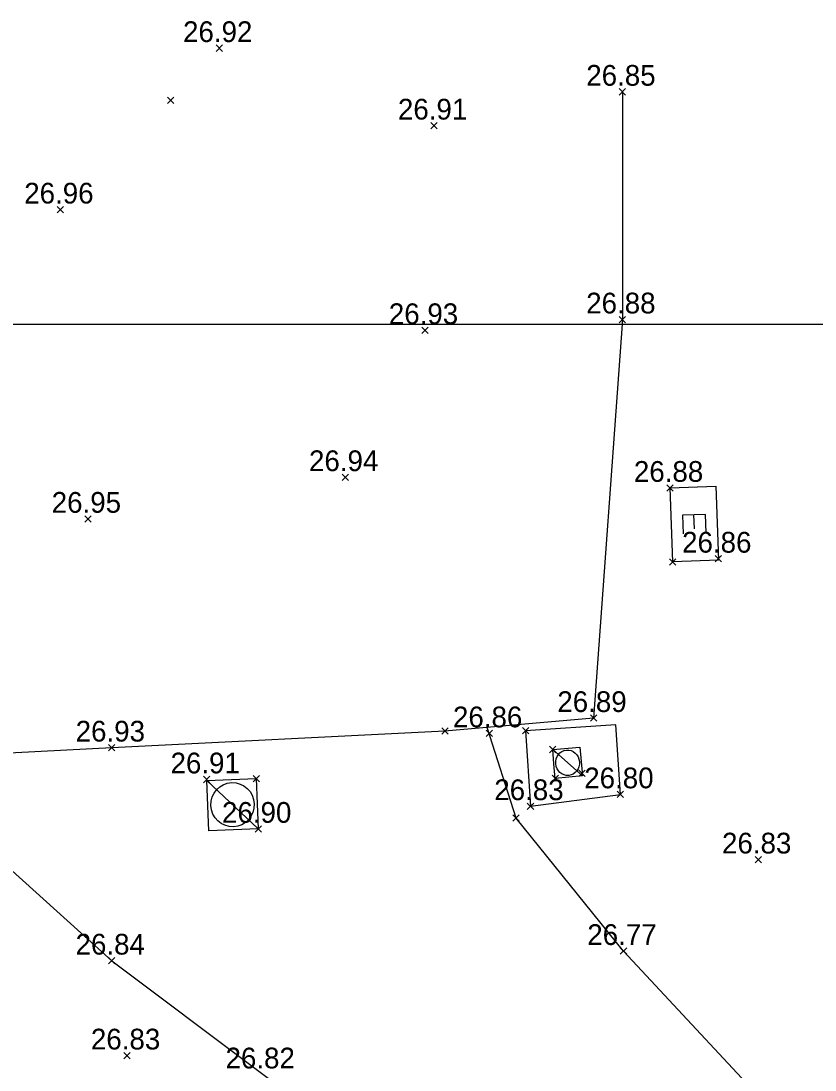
# Model space of a CAD drawing. Extents: x 37864 to 38032, y 453991 to 454052.
# Drawn here: x 37923.19 to 37934.11, y 454037.97 to 454052.39 of the extents above; entities that cross this region are included whole.
import ezdxf

# ---------------------------------------------------------------- set-up
doc = ezdxf.new("R2010")
doc.units = 0
for name, color, linetype in [('DH_CALCUL SURFACE-TEXTE', 7, 'Continuous'), ('DH_TEXTE', 7, 'Continuous'), ('GO_POTEAU', 7, 'Continuous'), ('PS_Mid', 7, 'Continuous'), ('PS_Pos', 7, 'Continuous'), ('SO_MENUISERIE EXT DOR', 7, 'Continuous'), ('SO_SANITAIRE DETAILLE', 7, 'Continuous')]:
    doc.layers.add(name, color=color, linetype=linetype)

# ---------------------------------------------------------------- blocks, each defined once
blk = doc.blocks.new('A-REGARD')
for p, q in [((0, 1), (1, 1)), ((0, 0), (1, 1)), ((0, 0), (0, 1)), ((1, 1), (1, 0)), ((0.5, 0), (0, 0)), ((1, 0), (0.5, 0))]:
    blk.add_line(p, q)
blk.add_circle((0.5, 0.5), 0.438)
blk = doc.blocks.new('V-TAMPON')
for p, q in [((0, 0), (0, 1)), ((0, 1), (1, 1)), ((1, 1), (1, 0)), ((0.375, 0.75), (0.375, 0.25)), ((0.625, 0.75), (0.375, 0.75)), ((0.562, 0.5), (0.375, 0.5)), ((0.375, 0.25), (0.625, 0.25)), ((1, 0), (0, 0))]:
    blk.add_line(p, q)
blk = doc.blocks.new('POINT_DISPLAY')
for p, q in [((-0.04375, -0.04375), (0.04375, 0.04375)), ((-0.04375, 0.04375), (0.04375, -0.04375))]:
    blk.add_line(p, q)
blk = doc.blocks.new('POINTCOT')
blk.add_blockref('POINT_DISPLAY', (0, 0))

msp = doc.modelspace()

# ---------------------------------------------------------------- linework, layer by layer
at = {"layer": 'DEFPOINTS'}
msp.add_lwpolyline([(37864.064, 453990.816), (37946.064, 453990.816), (37946.064, 454048.216), (37864.064, 454048.216)], close=True, dxfattribs=at)
at = {"layer": 'PS_Mid'}
msp.add_lwpolyline([(37930.129, 454042.632), (37930.196, 454041.595), (37931.433, 454041.758), (37931.371, 454042.712), (37930.129, 454042.632)], dxfattribs=at)
at = {"layer": 'SO_SANITAIRE DETAILLE'}
for points in [[(37931.461, 454051.412), (37931.46, 454048.283), (37931.063, 454042.806), (37929.02, 454042.628), (37924.438, 454042.4), (37918.697, 454042.102), (37913.082, 454041.936), (37907.417, 454041.715), (37901.195, 454041.497), (37895.602, 454041.336), (37888.675, 454041.141), (37884.765, 454041.024), (37878.173, 454040.907), (37873.078, 454041.057), (37866.515, 454040.532)], [(37939.024, 454033.13), (37936.384, 454034.931), (37933.79, 454037.12), (37931.475, 454039.605), (37929.998, 454041.432), (37929.601, 454042.679)], [(37921.361, 454042.24), (37924.438, 454039.473), (37928.39, 454036.508), (37931.87, 454034.006), (37934.645, 454032.123), (37937.958, 454030.315)]]:
    msp.add_lwpolyline(points, dxfattribs=at)

# ---------------------------------------------------------------- block references
at = {"layer": 'DH_CALCUL SURFACE-TEXTE', "rotation": 2.2526485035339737e-05}
for p in [(37925.916, 454052.012), (37931.461, 454051.412), (37925.247, 454051.294), (37928.871, 454050.947), (37923.732, 454049.793), (37931.46, 454048.283), (37928.746, 454048.136), (37927.648, 454046.116), (37932.116, 454045.969), (37924.11, 454045.544), (37932.153, 454044.952), (37932.779, 454044.996), (37931.063, 454042.806), (37929.02, 454042.628), (37929.628, 454042.597), (37930.129, 454042.632), (37924.438, 454042.4), (37930.501, 454042.375), (37930.905, 454042.048), (37925.744, 454041.963), (37926.425, 454041.976), (37930.537, 454041.977), (37931.433, 454041.758), (37930.196, 454041.595), (37929.998, 454041.432), (37926.452, 454041.284), (37933.328, 454040.862), (37931.475, 454039.605), (37924.438, 454039.473), (37924.649, 454038.169)]:
    msp.add_blockref('POINTCOT', p, dxfattribs=at)
at = {"layer": 'DH_TEXTE', "xscale": 0.3997961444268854, "yscale": 0.3748162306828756, "rotation": -84.7853401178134}
msp.add_blockref('A-REGARD', (37930.501, 454042.375), dxfattribs=at)
at = {"layer": 'PS_Pos', "xscale": 1.0175689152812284, "yscale": 0.6273642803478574, "rotation": -87.86707512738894}
msp.add_blockref('V-TAMPON', (37932.116, 454045.969), dxfattribs=at)
at = {"layer": 'SO_MENUISERIE EXT DOR', "xscale": 0.6923336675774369, "yscale": 0.6807626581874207, "rotation": 92.21839847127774}
msp.add_blockref('A-REGARD', (37926.452, 454041.284), dxfattribs=at)

# ---------------------------------------------------------------- texts
at = {"layer": 'GO_POTEAU'}
for s, p in [('26.92', (37925.418, 454052.096)), ('26.85', (37930.963, 454051.496)), ('26.91', (37928.373, 454051.031)), ('26.96', (37923.234, 454049.877)), ('26.88', (37930.962, 454048.367)), ('26.93', (37928.248, 454048.22)), ('26.94', (37927.15, 454046.2)), ('26.88', (37931.618, 454046.053)), ('26.95', (37923.612, 454045.628)), ('26.86', (37932.281, 454045.08)), ('26.89', (37930.565, 454042.89)), ('26.86', (37929.13, 454042.68)), ('26.93', (37923.941, 454042.484)), ('26.91', (37925.246, 454042.047)), ('26.80', (37930.935, 454041.842)), ('26.83', (37929.698, 454041.679)), ('26.90', (37925.954, 454041.368)), ('26.83', (37932.83, 454040.946)), ('26.77', (37930.977, 454039.689)), ('26.84', (37923.94, 454039.557)), ('26.83', (37924.151, 454038.253)), ('26.82', (37926.002, 454037.993))]:
    msp.add_text(s, height=0.285, rotation=0, dxfattribs=at).set_placement(p)

doc.saveas('drawing.dxf')
